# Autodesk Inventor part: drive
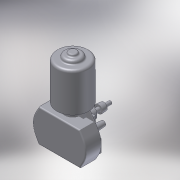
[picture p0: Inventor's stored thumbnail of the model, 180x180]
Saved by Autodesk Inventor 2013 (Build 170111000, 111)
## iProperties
Shininess: 25.0
Length Units: 11269
Angle Units: 11279
Time Units: 11290
Mass Units: 11283
Length Display Precision: 3
Angle Display Precision: 2
Created: 2002-03
Part Number: drive
Material: Steel, Mild
Document SubType Name: Modeling
Designer: =<Author>
Density: 7.86 g/cm^3
Description: =<Part Number>
Density: 7.86
Volumn: 410.8614142272902
Area: 307.483380970101
PropertySet Name: Model Information
Control State: 0
Master: False
Checked Out: True
Last Check In Date: 2008-10-15
Checked Out Date: 2008-10-15
Author: LAlexey
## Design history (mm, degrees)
sketch "Sketch1"
  geometry: C1 r 38.5 at (-17.032, 9.732)
  constraints: 1 centre point
  dimensions: "d0" = 77 diameter of C1
extrude "Extrusion1" new body sketch "Sketch1" distance "d1" = 93; taper "d2" = 0 deg
sketch "Sketch2"
  geometry: C1 r 38.5 at (0, 0) reference; C2 r 21 at (0, 0)
  constraints: 1 centre point, 1 coincident
  dimensions: "d3" = 42 diameter of C2
extrude "Extrusion2" join sketch "Sketch2" distance "d4" = 8; taper "d5" = 0 deg
sketch "Sketch3"
  geometry: C1 r 21 at (0, 0) reference; C2 r 10 at (0, 0)
  constraints: 1 centre point, 1 coincident
  dimensions: "d6" = 20 diameter of C2
extrude "Extrusion3" join sketch "Sketch3" distance "d7" = 5; taper "d8" = 0 deg
fillet "Fillet1" dims "d9" = 6
fillet "Fillet2" dims "d10" = 6
fillet "Fillet3" dims "d11" = 3
fillet "Fillet4" dims "d12" = 3
fillet "Fillet5" dims "d13" = 3
sketch "Sketch4"
  geometry: C1 r 38.5 at (0, 0) reference; C2 r 20 at (0, 0)
  constraints: 1 centre point, 1 coincident
  dimensions: "d14" = 40 diameter of C2
extrude "Extrusion4" join sketch "Sketch4" distance "d15" = 18; taper "d16" = 0 deg
sketch "Sketch5"
  geometry: C1 r 20 at (0, 0) reference; C2 r 38.5 at (0, 0) reference
extrude "Extrusion5" join sketch "Sketch5" distance "d17" = 10; taper "d18" = 0 deg
chamfer "Chamfer1" distance "d19" = 10; stored, may be unused: angle "d20" = 60 deg, second distance "d95" = 10
workaxis "Work Axis1"
workplane "Work Plane1"
sketch "Sketch6"
  geometry: L1 (-30, -4.5)-(30, -4.5); L2 (30, -4.5)-(30, 4.5); L3 (30, 4.5)-(-30, 4.5); L4 (-30, 4.5)-(-30, -4.5); C1 r 20 at (0, 0) reference
  constraints: 8 end point, 2 parallel, 1 horizontal, 1 perpendicular
  dimensions: "d21" = 9 distance between parallel lines of L3 L1; "d22" = 4.5 distance from line of C1.centre L3; "d23" = 60 distance between parallel lines of L2 L4; "d24" = 30 distance from line of C1.centre L4
extrude "Extrusion6" join sketch "Sketch6" distance "d25" = 20; taper "d26" = 0 deg
sketch "Sketch7"
  geometry: L1 (0, 0)-(10.513, 0) reference; L2 (29.49, 0)-(52.178, 40.396); L3 (52.178, 40.396)-(30.513, 79); L4 (30.513, 79)-(-69.487, 79); L5 (-69.487, 79)-(-91.166, 40.403); L6 (-91.166, 40.403)-(-68.491, 0); L7 (-49.487, 0)-(-49.487, -13.286) reference; L8 (19.013, -18)-(-57.987, -18) reference; L9 (17.7, -18)-(29.49, 0); L10 (-68.491, 0)-(-56.7, -18); L11 (-19.487, 119.6)-(-19.487, -164.6) reference
  constraints: 14 end point, 3 equal length, 3 parallel, 2 point on line, 2 other
  dimensions: "d27" = 97 distance between parallel lines of L8 L4; "d28" = 100 distance of L3.end L4.end; "d29" = 50 distance from line of L3.end L11; "d30" = 125 distance between parallel lines of L6 L3; "d31" = 124.98352 distance between parallel lines of L2 L5; "d32" = 79 distance from line of L2.start L4
extrude "Extrusion7" join sketch "Sketch7" distance "d33" = 2.5; taper "d34" = 0 deg
fillet "Fillet6" dims "d35" = 51
fillet "Fillet7" dims "d36" = 51
workaxis "Work Axis2"
workaxis "Work Axis3"
sketch "Sketch8"
  geometry: L1 (29.49, 0)-(38.156, -15.43) reference; L2 (-77.152, -15.433)-(-68.491, 0) reference; L3 (-69.487, -79)-(-77.144, -65.368) reference; L4 (30.513, -79)-(-69.487, -79) reference; L5 (38.165, -65.365)-(30.513, -79) reference; L6 (-68.491, 0)-(29.49, 0); A1 r 51 centre (-6.31, -40.405) between (38.165, -65.365) and (38.156, -15.43) reference; A2 r 51 centre (-32.677, -40.393) between (-77.152, -15.433) and (-77.144, -65.368) reference
  constraints: 2 end point
extrude "Extrusion8" join sketch "Sketch8" distance "d37" = 35; taper "d38" = 0 deg
fillet "Fillet8" dims "d39" = 3
sketch "Sketch9"
  geometry: L1 (69.487, 79)-(-30.513, 79) reference; L2 (19.487, 119.6)-(19.487, -164.6) reference; C1 r 15.5 at (-11.653, 59)
  constraints: 1 centre point
  dimensions: "d40" = 31 diameter of C1; "d41" = 20 distance from line of L1 C1.centre; "d77" = 31.14 distance from line of L2 C1.centre
extrude "Extrusion9" join sketch "Sketch9" distance "d43" = 45; taper "d44" = -2 deg
sketch "Sketch10"
  geometry: C1 r 13.929 at (0, 0) reference; C2 r 12 at (0, 0)
  constraints: 1 centre point, 1 coincident
  dimensions: "d45" = 24 diameter of C2
extrude "Extrusion10" join sketch "Sketch10" distance "d46" = 30; taper "d47" = 0 deg
fillet "Fillet9" dims "d48" = 3
sketch "Sketch11"
  geometry: C1 r 12 at (0, 0) reference; C2 r 5 at (0, 0)
  constraints: 1 centre point, 1 coincident
  dimensions: "d49" = 10 diameter of C2
extrude "Extrusion11" join sketch "Sketch11" distance "d50" = 14; taper "d51" = 0 deg
sketch "Sketch12"
  geometry: C1 r 5 at (0, 0) reference; C2 r 9.75 at (0, 0)
  constraints: 1 centre point, 1 coincident
  dimensions: "d52" = 19.5 diameter of C2
extrude "Extrusion12" join sketch "Sketch12" distance "d53" = 12; taper "d54" = -4 deg
sketch "Sketch13"
  geometry: C1 r 8.911 at (0, 0) reference; C2 r 4 at (0, 0)
  constraints: 1 centre point, 1 coincident
  dimensions: "d55" = 8 diameter of C2
extrude "Extrusion13" join sketch "Sketch13" distance "d56" = 16; taper "d57" = 0 deg
sketch "Sketch14"
  geometry: C1 r 18.397 at (-11.653, 59) reference; C2 r 9 at (43.647, 39)
  constraints: 1 centre point
  dimensions: "d58" = 18 diameter of C2; "d59" = 55.3 horizontal distance of C1.centre C2.centre; "d60" = 20 vertical distance of C2.centre C1.centre
extrude "Extrusion14" join sketch "Sketch14" distance "d61" = 45; taper "d62" = -4 deg
sketch "Sketch15"
  geometry: L1 (38.974, 0)-(0, 0) reference; L2 (40.183, -8)-(38.974, -8) reference; L3 (-25.601, 59.122)-(-25.601, 0); L4 (-25.601, 0)-(56.399, 0); L5 (56.399, 0)-(56.399, 47.829); L6 (56.399, 47.829)-(2.964, 47.829); L7 (2.964, 47.829)-(2.964, 59.122); L8 (2.964, 59.122)-(-25.601, 59.122); 1 further point
  constraints: 12 end point, 4 perpendicular, 2 parallel, 2 other
  dimensions: "d63" = 0 distance between parallel lines of L1 L4; "d64" = 82 distance between parallel lines of L3 L5
extrude "Extrusion15" join sketch "Sketch15" distance "d65" = 13; taper "d66" = 0 deg
sketch "Sketch16"
  geometry: L1 (119.216, -0.094)-(52.716, -0.094); L2 (52.716, -0.094)-(52.716, -31.094); L3 (52.716, -31.094)-(119.216, -31.094); L4 (119.216, -31.094)-(119.216, -0.094); L5 (75.905, -31.171)-(86.912, -31.171) reference; L6 (86.912, -31.171)-(86.912, -79) reference; L7 (86.912, -79)-(69.487, -79) reference; L8 (69.487, -87)-(69.487, -79) reference; L9 (70.696, -87)-(69.487, -87) reference; L10 (87.474, -96.563)-(98.977, -79) reference; L11 (98.977, -79)-(107.644, -63.57) reference; L12 (107.652, -13.635)-(100, 0) reference; L13 (100, 0)-(0, 0) reference; L14 (0, 0)-(-7.657, -13.632) reference; L15 (-7.665, -63.567)-(0.996, -79) reference; L16 (0.996, -79)-(12.507, -96.574) reference; L17 (30.513, -87)-(29.304, -87) reference; L18 (30.513, -79)-(30.513, -87) reference; L19 (30.513, -79)-(4.912, -79) reference; L20 (4.912, -79)-(4.912, -31.996) reference; L21 (33.477, -31.171)-(72.415, -31.171) reference; A1 r 51 centre (63.177, -38.595) between (107.644, -63.57) and (107.652, -13.635) reference; A2 r 51 centre (36.81, -38.607) between (-7.657, -13.632) and (-7.665, -63.567) reference; A3 r 18.397 centre (18.86, -20) between (33.477, -31.171) and (4.912, -31.996) reference; A4 r 9 centre (74.16, -40) between (75.905, -31.171) and (72.415, -31.171) reference; 2 further points
  constraints: 8 end point, 2 parallel, 1 horizontal, 1 perpendicular, 4 other
  dimensions: "d67" = 31 distance between parallel lines of L3 L1; "d68" = 66.5 distance between parallel lines of L2 L4
extrude "Extrusion16" join sketch "Sketch16" distance "d69" = 29; taper "d70" = 0 deg
sketch "Sketch17"
  geometry: L1 (11.653, -59)-(50.627, -59) reference; L2 (69.64, -77)-(-7.36, -77) reference; L3 (10, -6.633)-(10, 6.633); L4 (-10, -6.633)-(-10, 6.633); L5 (31.14, 60.6)-(31.14, -223.6) reference; A1 r 12 centre (0, 0) between (10, -6.633) and (10, 6.633) reference
  constraints: 4 end point, 4 point on circle, 2 parallel, 1 perpendicular
  dimensions: "d73" = 20 distance between parallel lines of L4 L3; "d74" = 10 distance from line of A1.centre L4
extrude "Extrusion17" cut sketch "Sketch17" distance "d75" = 24; taper "d76" = 0 deg
sketch "Sketch18"
  geometry: C1 r 5.853 at (0, 0) reference; C2 r 3 at (0, 0)
  constraints: 1 centre point, 1 coincident
  dimensions: "d78" = 6 diameter of C2
extrude "Extrusion18" cut sketch "Sketch18" distance "d79" = 12; taper "d80" = 0 deg
sketch "Эскиз19"
  geometry: L1 (75.905, -31.171)-(86.912, -31.171) reference; L2 (86.912, -31.171)-(86.912, -79) reference; L3 (33.477, -31.171)-(72.415, -31.171) reference; L4 (43.912, -4.671)-(43.912, -26.671); L5 (43.912, -26.671)-(75.912, -26.671); L6 (75.912, -26.671)-(75.912, -30.671); L7 (75.912, -30.671)-(93.912, -30.671); L8 (93.912, -30.671)-(93.912, -0.671); L9 (93.912, -0.671)-(75.912, -0.671); L10 (75.912, -0.671)-(75.912, -4.671); L11 (75.912, -4.671)-(43.912, -4.671); L12 (33.477, -31.171)-(86.912, -31.171) reference
  constraints: 16 end point, 5 perpendicular, 4 parallel, 1 collinear
  dimensions: "d82" = 50 distance between parallel lines of L4 L8; "d84" = 30 distance of L7.end L8.end; "d85" = 22 distance of L4.start L4.end; "d86" = 7 distance between parallel lines of L2 L8; "d87" = 0.5 distance between parallel lines of L1 L7; "d93" = 18 distance of L8.end L9.end; "d94" = 18 distance of L6.end L7.end
extrude "Выдавливание19" join sketch "Эскиз19" distance "d88" = 20; taper "d89" = 0 deg
chamfer "Фаска2" distance "d90" = 7; stored, may be unused: second distance "d91" = 15, angle "d96" = 45 deg
fillet "Сопряжение10" dims "d92" = 5
body "Solid1"
